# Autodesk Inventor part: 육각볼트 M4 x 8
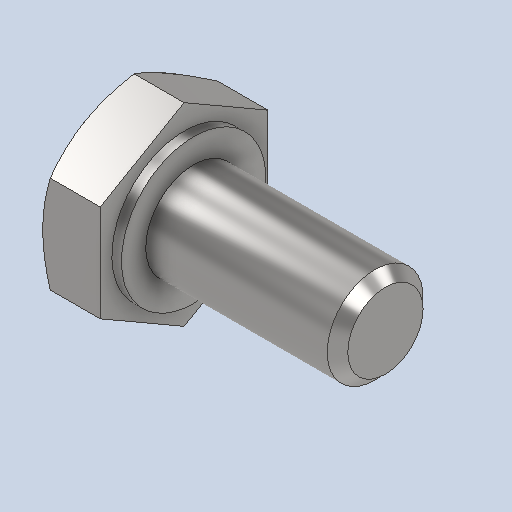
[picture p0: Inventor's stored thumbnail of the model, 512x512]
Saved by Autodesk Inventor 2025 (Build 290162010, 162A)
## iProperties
Created: 2024-07
Part Number: 육각볼트 M4 x 8
Material: 강철, 연강
Description: 6각 머리 나사
Document SubType Name: Modeling
Designer: 학생
Density: 7.86 g/cm^3
Appearance: 기본값
Author: jhkim
Sending System: Autodesk Inventor 2025
Preprocessor: ST-DEVELOPER v20
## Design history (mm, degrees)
feature "Solid1"
node "솔리드1"
